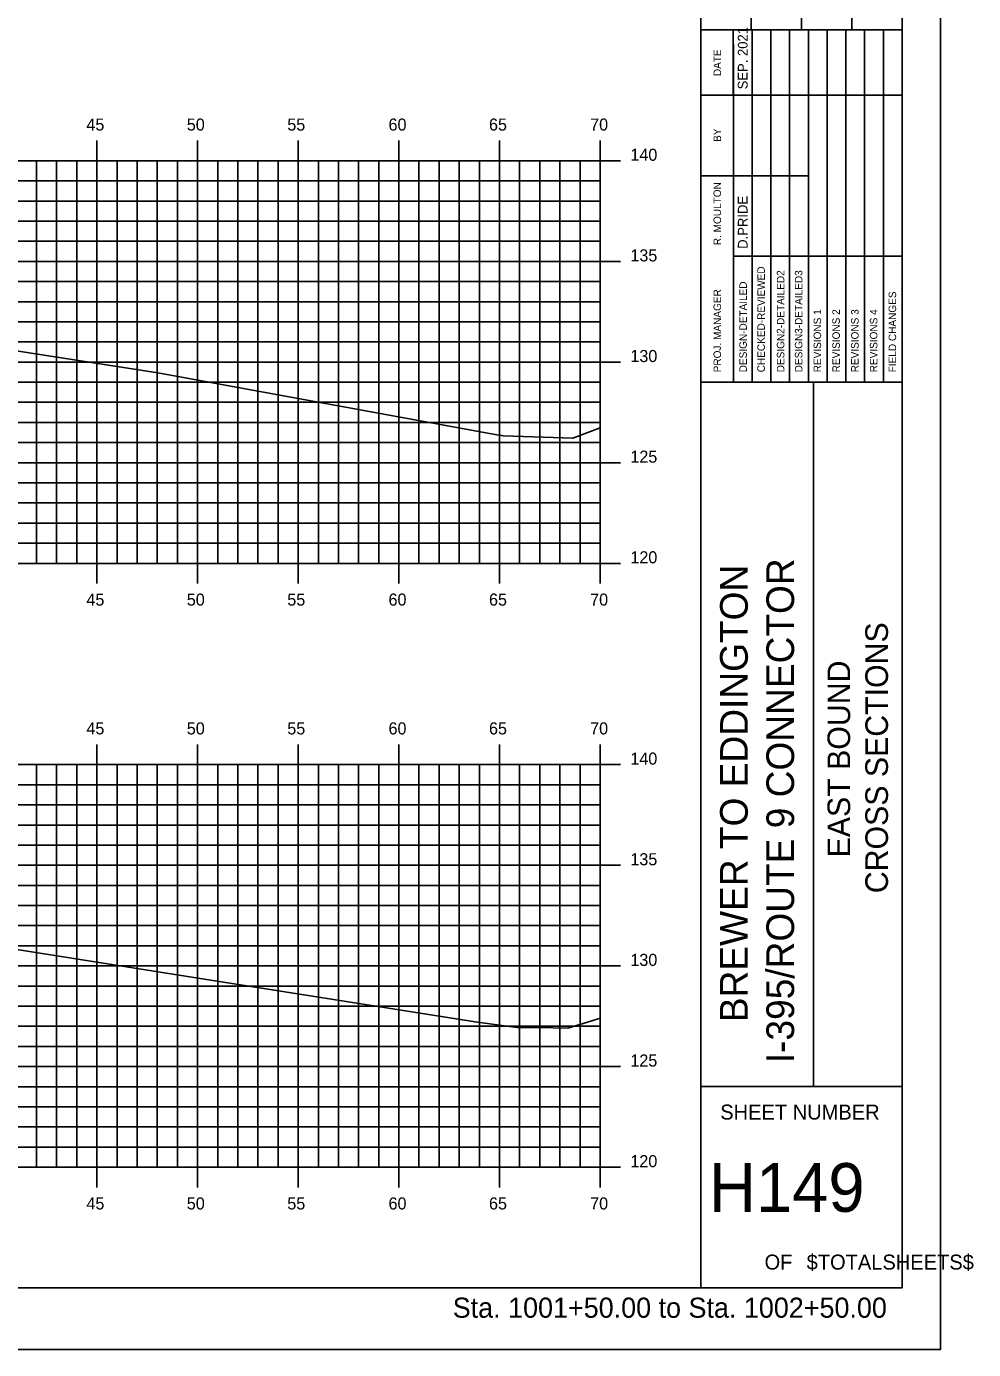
# Model space of a CAD drawing. Extents: x 850851 to 851023, y 365624 to 365734.
# Drawn here: x 850976 to 851023, y 365624 to 365689.7 of the extents above; entities that cross this region are included whole.
import ezdxf

# ---------------------------------------------------------------- set-up
doc = ezdxf.new("R2010")
doc.units = 0
for name, color, linetype in [('BORDER', 7, 'Continuous'), ('H_V ANNOTATION', 7, 'Continuous'), ('MAJOR', 7, 'Continuous'), ('MINOR', 7, 'Continuous'), ('PLOT BOUNDARY', 7, 'Continuous'), ('S_Roadway_Centerline', 7, 'Continuous')]:
    doc.layers.add(name, color=color, linetype=linetype)

msp = doc.modelspace()

# ---------------------------------------------------------------- linework, layer by layer
at = {"layer": 'BORDER'}
for p, q in [((851009.496, 365627.027), (851009.496, 365732.027)), ((851011.996, 365689.53), (851011.996, 365698.177)), ((851014.496, 365689.53), (851014.496, 365698.177)), ((851016.996, 365689.53), (851016.996, 365698.177)), ((851009.496, 365689.53), (851019.496, 365689.53)), ((851009.496, 365672.03), (851019.496, 365672.03)), ((851015.087, 365637.03), (851015.087, 365672.03)), ((851009.496, 365637.03), (851019.496, 365637.03))]:
    msp.add_line(p, q, dxfattribs=at)
msp.add_lwpolyline([(850859.496, 365627.027), (851019.496, 365627.027), (851019.496, 365732.027), (850859.496, 365732.027)], close=True, dxfattribs=at)
for points in [[(851011.111, 365686.28), (851011.111, 365689.53)], [(851012.044, 365672.033), (851012.044, 365689.53)], [(851012.975, 365689.53), (851012.975, 365672.033)], [(851013.907, 365672.033), (851013.907, 365689.53)], [(851014.839, 365672.033), (851014.839, 365689.53)], [(851015.77, 365672.033), (851015.77, 365689.53)], [(851016.702, 365672.033), (851016.702, 365689.53)], [(851017.634, 365672.033), (851017.634, 365689.53)], [(851018.565, 365672.033), (851018.565, 365689.53)], [(851011.112, 365672.033), (851011.112, 365688.824)], [(851009.496, 365686.28), (851019.496, 365686.28)], [(851009.496, 365682.28), (851011.112, 365682.28)], [(851011.111, 365682.28), (851014.838, 365682.28)], [(851011.111, 365678.28), (851019.496, 365678.28)]]:
    msp.add_lwpolyline(points, dxfattribs=at)
at = {"layer": 'MAJOR'}
for p, q in [((850979.496, 365684.029), (850979.496, 365683.027)), ((850984.496, 365684.029), (850984.496, 365683.027)), ((850989.496, 365684.029), (850989.496, 365683.027)), ((850994.496, 365684.029), (850994.496, 365683.027)), ((850999.496, 365684.029), (850999.496, 365683.027)), ((851004.496, 365684.029), (851004.496, 365683.027)), ((850864.496, 365683.027), (851004.496, 365683.027)), ((850864.496, 365683.027), (851004.496, 365683.027)), ((850979.496, 365663.027), (850979.496, 365683.027)), ((850984.496, 365663.027), (850984.496, 365683.027)), ((850989.496, 365663.027), (850989.496, 365683.027)), ((850994.496, 365663.027), (850994.496, 365683.027)), ((850999.496, 365663.027), (850999.496, 365683.027)), ((851005.498, 365683.027), (851003.494, 365683.027)), ((851004.496, 365663.027), (851004.496, 365683.027)), ((851004.496, 365663.027), (851004.496, 365683.027)), ((850864.496, 365678.027), (851004.496, 365678.027)), ((851005.498, 365678.027), (851003.494, 365678.027)), ((850864.496, 365673.027), (851004.496, 365673.027)), ((851005.498, 365673.027), (851003.494, 365673.027)), ((850864.496, 365668.027), (851004.496, 365668.027)), ((851005.498, 365668.027), (851003.494, 365668.027)), ((850864.496, 365663.027), (851004.496, 365663.027)), ((850864.496, 365663.027), (851004.496, 365663.027)), ((850979.496, 365662.025), (850979.496, 365663.027)), ((850984.496, 365662.025), (850984.496, 365663.027)), ((850989.496, 365662.025), (850989.496, 365663.027)), ((850994.496, 365662.025), (850994.496, 365663.027)), ((850999.496, 365662.025), (850999.496, 365663.027)), ((851005.498, 365663.027), (851003.494, 365663.027)), ((851004.496, 365662.025), (851004.496, 365663.027)), ((850979.496, 365654.029), (850979.496, 365653.027)), ((850984.496, 365654.029), (850984.496, 365653.027)), ((850989.496, 365654.029), (850989.496, 365653.027)), ((850994.496, 365654.029), (850994.496, 365653.027)), ((850999.496, 365654.029), (850999.496, 365653.027)), ((851004.496, 365654.029), (851004.496, 365653.027)), ((850864.496, 365653.027), (851004.496, 365653.027)), ((850864.496, 365653.027), (851004.496, 365653.027)), ((850979.496, 365633.027), (850979.496, 365653.027)), ((850984.496, 365633.027), (850984.496, 365653.027)), ((850989.496, 365633.027), (850989.496, 365653.027)), ((850994.496, 365633.027), (850994.496, 365653.027)), ((850999.496, 365633.027), (850999.496, 365653.027)), ((851005.498, 365653.027), (851003.494, 365653.027)), ((851004.496, 365633.027), (851004.496, 365653.027)), ((851004.496, 365633.027), (851004.496, 365653.027)), ((850864.496, 365648.027), (851004.496, 365648.027)), ((851005.498, 365648.027), (851003.494, 365648.027)), ((850864.496, 365643.027), (851004.496, 365643.027)), ((851005.498, 365643.027), (851003.494, 365643.027)), ((850864.496, 365638.027), (851004.496, 365638.027)), ((851005.498, 365638.027), (851003.494, 365638.027)), ((850864.496, 365633.027), (851004.496, 365633.027)), ((850864.496, 365633.027), (851004.496, 365633.027)), ((850979.496, 365632.025), (850979.496, 365633.027)), ((850984.496, 365632.025), (850984.496, 365633.027)), ((850989.496, 365632.025), (850989.496, 365633.027)), ((850994.496, 365632.025), (850994.496, 365633.027)), ((850999.496, 365632.025), (850999.496, 365633.027)), ((851005.498, 365633.027), (851003.494, 365633.027)), ((851004.496, 365632.025), (851004.496, 365633.027))]:
    msp.add_line(p, q, dxfattribs=at)
at = {"layer": 'MINOR'}
for p, q in [((850976.496, 365663.027), (850976.496, 365683.027)), ((850977.496, 365663.027), (850977.496, 365683.027)), ((850978.496, 365663.027), (850978.496, 365683.027)), ((850980.496, 365663.027), (850980.496, 365683.027)), ((850981.496, 365663.027), (850981.496, 365683.027)), ((850982.496, 365663.027), (850982.496, 365683.027)), ((850983.496, 365663.027), (850983.496, 365683.027)), ((850985.496, 365663.027), (850985.496, 365683.027)), ((850986.496, 365663.027), (850986.496, 365683.027)), ((850987.496, 365663.027), (850987.496, 365683.027)), ((850988.496, 365663.027), (850988.496, 365683.027)), ((850990.496, 365663.027), (850990.496, 365683.027)), ((850991.496, 365663.027), (850991.496, 365683.027)), ((850992.496, 365663.027), (850992.496, 365683.027)), ((850993.496, 365663.027), (850993.496, 365683.027)), ((850995.496, 365663.027), (850995.496, 365683.027)), ((850996.496, 365663.027), (850996.496, 365683.027)), ((850997.496, 365663.027), (850997.496, 365683.027)), ((850998.496, 365663.027), (850998.496, 365683.027)), ((851000.496, 365663.027), (851000.496, 365683.027)), ((851001.496, 365663.027), (851001.496, 365683.027)), ((851002.496, 365663.027), (851002.496, 365683.027)), ((851003.496, 365663.027), (851003.496, 365683.027)), ((850864.496, 365682.027), (851004.496, 365682.027)), ((851004.496, 365682.027), (851003.494, 365682.027)), ((850864.496, 365681.027), (851004.496, 365681.027)), ((851004.496, 365681.027), (851003.494, 365681.027)), ((850864.496, 365680.027), (851004.496, 365680.027)), ((851004.496, 365680.027), (851003.494, 365680.027)), ((850864.496, 365679.027), (851004.496, 365679.027)), ((851004.496, 365679.027), (851003.494, 365679.027)), ((850864.496, 365677.027), (851004.496, 365677.027)), ((851004.496, 365677.027), (851003.494, 365677.027)), ((850864.496, 365676.027), (851004.496, 365676.027)), ((851004.496, 365676.027), (851003.494, 365676.027)), ((850864.496, 365675.027), (851004.496, 365675.027)), ((851004.496, 365675.027), (851003.494, 365675.027)), ((850864.496, 365674.027), (851004.496, 365674.027)), ((851004.496, 365674.027), (851003.494, 365674.027)), ((850864.496, 365672.027), (851004.496, 365672.027)), ((851004.496, 365672.027), (851003.494, 365672.027)), ((850864.496, 365671.027), (851004.496, 365671.027)), ((851004.496, 365671.027), (851003.494, 365671.027)), ((850864.496, 365670.027), (851004.496, 365670.027)), ((851004.496, 365670.027), (851003.494, 365670.027)), ((850864.496, 365669.027), (851004.496, 365669.027)), ((851004.496, 365669.027), (851003.494, 365669.027)), ((850864.496, 365667.027), (851004.496, 365667.027)), ((851004.496, 365667.027), (851003.494, 365667.027)), ((850864.496, 365666.027), (851004.496, 365666.027)), ((851004.496, 365666.027), (851003.494, 365666.027)), ((850864.496, 365665.027), (851004.496, 365665.027)), ((851004.496, 365665.027), (851003.494, 365665.027)), ((850864.496, 365664.027), (851004.496, 365664.027)), ((851004.496, 365664.027), (851003.494, 365664.027)), ((850976.496, 365633.027), (850976.496, 365653.027)), ((850977.496, 365633.027), (850977.496, 365653.027)), ((850978.496, 365633.027), (850978.496, 365653.027)), ((850980.496, 365633.027), (850980.496, 365653.027)), ((850981.496, 365633.027), (850981.496, 365653.027)), ((850982.496, 365633.027), (850982.496, 365653.027)), ((850983.496, 365633.027), (850983.496, 365653.027)), ((850985.496, 365633.027), (850985.496, 365653.027)), ((850986.496, 365633.027), (850986.496, 365653.027)), ((850987.496, 365633.027), (850987.496, 365653.027)), ((850988.496, 365633.027), (850988.496, 365653.027)), ((850990.496, 365633.027), (850990.496, 365653.027)), ((850991.496, 365633.027), (850991.496, 365653.027)), ((850992.496, 365633.027), (850992.496, 365653.027)), ((850993.496, 365633.027), (850993.496, 365653.027)), ((850995.496, 365633.027), (850995.496, 365653.027)), ((850996.496, 365633.027), (850996.496, 365653.027)), ((850997.496, 365633.027), (850997.496, 365653.027)), ((850998.496, 365633.027), (850998.496, 365653.027)), ((851000.496, 365633.027), (851000.496, 365653.027)), ((851001.496, 365633.027), (851001.496, 365653.027)), ((851002.496, 365633.027), (851002.496, 365653.027)), ((851003.496, 365633.027), (851003.496, 365653.027)), ((850864.496, 365652.027), (851004.496, 365652.027)), ((851004.496, 365652.027), (851003.494, 365652.027)), ((850864.496, 365651.027), (851004.496, 365651.027)), ((851004.496, 365651.027), (851003.494, 365651.027)), ((850864.496, 365650.027), (851004.496, 365650.027)), ((851004.496, 365650.027), (851003.494, 365650.027)), ((850864.496, 365649.027), (851004.496, 365649.027)), ((851004.496, 365649.027), (851003.494, 365649.027)), ((850864.496, 365647.027), (851004.496, 365647.027)), ((851004.496, 365647.027), (851003.494, 365647.027)), ((850864.496, 365646.027), (851004.496, 365646.027)), ((851004.496, 365646.027), (851003.494, 365646.027)), ((850864.496, 365645.027), (851004.496, 365645.027)), ((851004.496, 365645.027), (851003.494, 365645.027)), ((850864.496, 365644.027), (851004.496, 365644.027)), ((851004.496, 365644.027), (851003.494, 365644.027)), ((850864.496, 365642.027), (851004.496, 365642.027)), ((851004.496, 365642.027), (851003.494, 365642.027)), ((850864.496, 365641.027), (851004.496, 365641.027)), ((851004.496, 365641.027), (851003.494, 365641.027)), ((850864.496, 365640.027), (851004.496, 365640.027)), ((851004.496, 365640.027), (851003.494, 365640.027)), ((850864.496, 365639.027), (851004.496, 365639.027)), ((851004.496, 365639.027), (851003.494, 365639.027)), ((850864.496, 365637.027), (851004.496, 365637.027)), ((851004.496, 365637.027), (851003.494, 365637.027)), ((850864.496, 365636.027), (851004.496, 365636.027)), ((851004.496, 365636.027), (851003.494, 365636.027)), ((850864.496, 365635.027), (851004.496, 365635.027)), ((851004.496, 365635.027), (851003.494, 365635.027)), ((850864.496, 365634.027), (851004.496, 365634.027)), ((851004.496, 365634.027), (851003.494, 365634.027))]:
    msp.add_line(p, q, dxfattribs=at)
at = {"layer": 'PLOT BOUNDARY'}
msp.add_lwpolyline([(850851.403, 365623.968), (851021.403, 365623.968), (851021.403, 365733.968), (850851.403, 365733.968)], close=True, dxfattribs=at)
at = {"layer": 'S_Roadway_Centerline'}
for points in [[(850917.187, 365671.156), (850928.976, 365673.159), (850930.6, 365673.434), (850930.974, 365673.369), (850933.274, 365673.491), (850943.657, 365674.123), (850946.409, 365674.339), (850946.89, 365674.241), (850947.06, 365674.249), (850959.735, 365674.832), (850963.529, 365674.924), (850966.679, 365674.819), (850967.512, 365674.708), (850973.662, 365673.86), (850982.515, 365672.487), (850999.367, 365669.418), (850999.593, 365669.377), (850999.701, 365669.367), (851003.131, 365669.253), (851004.496, 365669.757)], [(850927.869, 365643.356), (850930.484, 365643.789), (850930.631, 365643.818), (850931.158, 365643.765), (850931.729, 365643.789), (850933.655, 365643.859), (850944.6, 365644.522), (850946.236, 365644.691), (850947.929, 365644.648), (850948.697, 365644.668), (850966.304, 365645.223), (850966.771, 365645.236), (850966.888, 365645.217), (850968.7, 365644.924), (850984.525, 365642.416), (850998.292, 365640.256), (851000.356, 365639.969), (851001.414, 365639.96), (851002.897, 365639.934), (851004.086, 365640.301), (851004.496, 365640.427)]]:
    msp.add_lwpolyline(points, dxfattribs=at)

# ---------------------------------------------------------------- texts
at = {"layer": 'BORDER'}
for s, height, p in [('SEP. 2021', 0.4845, (851011.819, 365686.575)), ('DATE', 0.3714, (851010.5, 365687.235)), ('BY', 0.3714, (851010.5, 365683.965)), ('R. MOULTON', 0.3727, (851010.5, 365678.832)), ('D.PRIDE', 0.4845, (851011.819, 365678.653)), ('CHECKED-REVIEWED', 0.37275, (851012.677, 365672.518)), ('DESIGN2-DETAILED2', 0.37275, (851013.646, 365672.518)), ('DESIGN3-DETAILED3', 0.37275, (851014.541, 365672.518)), ('DESIGN-DETAILED', 0.37275, (851011.783, 365672.518)), ('PROJ. MANAGER', 0.37275, (851010.5, 365672.518)), ('FIELD CHANGES', 0.37275, (851019.199, 365672.518)), ('REVISIONS 1', 0.37275, (851015.472, 365672.518)), ('REVISIONS 2', 0.37275, (851016.404, 365672.518)), ('REVISIONS 3', 0.37275, (851017.336, 365672.518)), ('REVISIONS 4', 0.37275, (851018.267, 365672.518)), ('I-395/ROUTE 9 CONNECTOR', 1.37787, (851014.131, 365638.192)), ('BREWER TO EDDINGTON', 1.37787, (851011.83, 365640.231)), ('CROSS SECTIONS', 1.125, (851018.794, 365646.638)), ('EAST BOUND', 1.125, (851016.915, 365648.418))]:
    msp.add_text(s, height=height, rotation=90, dxfattribs=at).set_placement(p)
for s, height, p in [('SHEET NUMBER', 0.74527, (851010.462, 365635.393)), ('H149', 2.4194, (851009.897, 365630.809)), ('$TOTALSHEETS$', 0.74527, (851014.753, 365627.94)), ('OF', 0.7453, (851012.663, 365627.94))]:
    msp.add_text(s, height=height, dxfattribs=at).set_placement(p)
at = {"layer": 'H_V ANNOTATION'}
for s, height, p in [('45', 0.6, (850978.974, 365684.527)), ('50', 0.6, (850983.961, 365684.527)), ('55', 0.6, (850988.953, 365684.527)), ('60', 0.6, (850993.982, 365684.527)), ('65', 0.6, (850998.974, 365684.527)), ('70', 0.6, (851003.998, 365684.527)), ('140', 0.6, (851005.996, 365683.027)), ('135', 0.6, (851005.996, 365678.027)), ('130', 0.6, (851005.996, 365673.027)), ('125', 0.6, (851005.996, 365668.027)), ('120', 0.6, (851005.996, 365663.027)), ('45', 0.6, (850978.974, 365660.927)), ('50', 0.6, (850983.961, 365660.927)), ('55', 0.6, (850988.953, 365660.927)), ('60', 0.6, (850993.982, 365660.927)), ('65', 0.6, (850998.974, 365660.927)), ('70', 0.6, (851003.998, 365660.927)), ('45', 0.6, (850978.974, 365654.527)), ('50', 0.6, (850983.961, 365654.527)), ('55', 0.6, (850988.953, 365654.527)), ('60', 0.6, (850993.982, 365654.527)), ('65', 0.6, (850998.974, 365654.527)), ('70', 0.6, (851003.998, 365654.527)), ('140', 0.6, (851005.996, 365653.027)), ('135', 0.6, (851005.996, 365648.027)), ('130', 0.6, (851005.996, 365643.027)), ('125', 0.6, (851005.996, 365638.027)), ('120', 0.6, (851005.996, 365633.027)), ('45', 0.6, (850978.974, 365630.927)), ('50', 0.6, (850983.961, 365630.927)), ('55', 0.6, (850988.953, 365630.927)), ('60', 0.6, (850993.982, 365630.927)), ('65', 0.6, (850998.974, 365630.927)), ('70', 0.6, (851003.998, 365630.927)), ('Sta. 1001+50.00 to Sta. 1002+50.00', 1.0002, (850997.172, 365625.547))]:
    msp.add_text(s, height=height, dxfattribs=at).set_placement(p)

doc.saveas('drawing.dxf')
